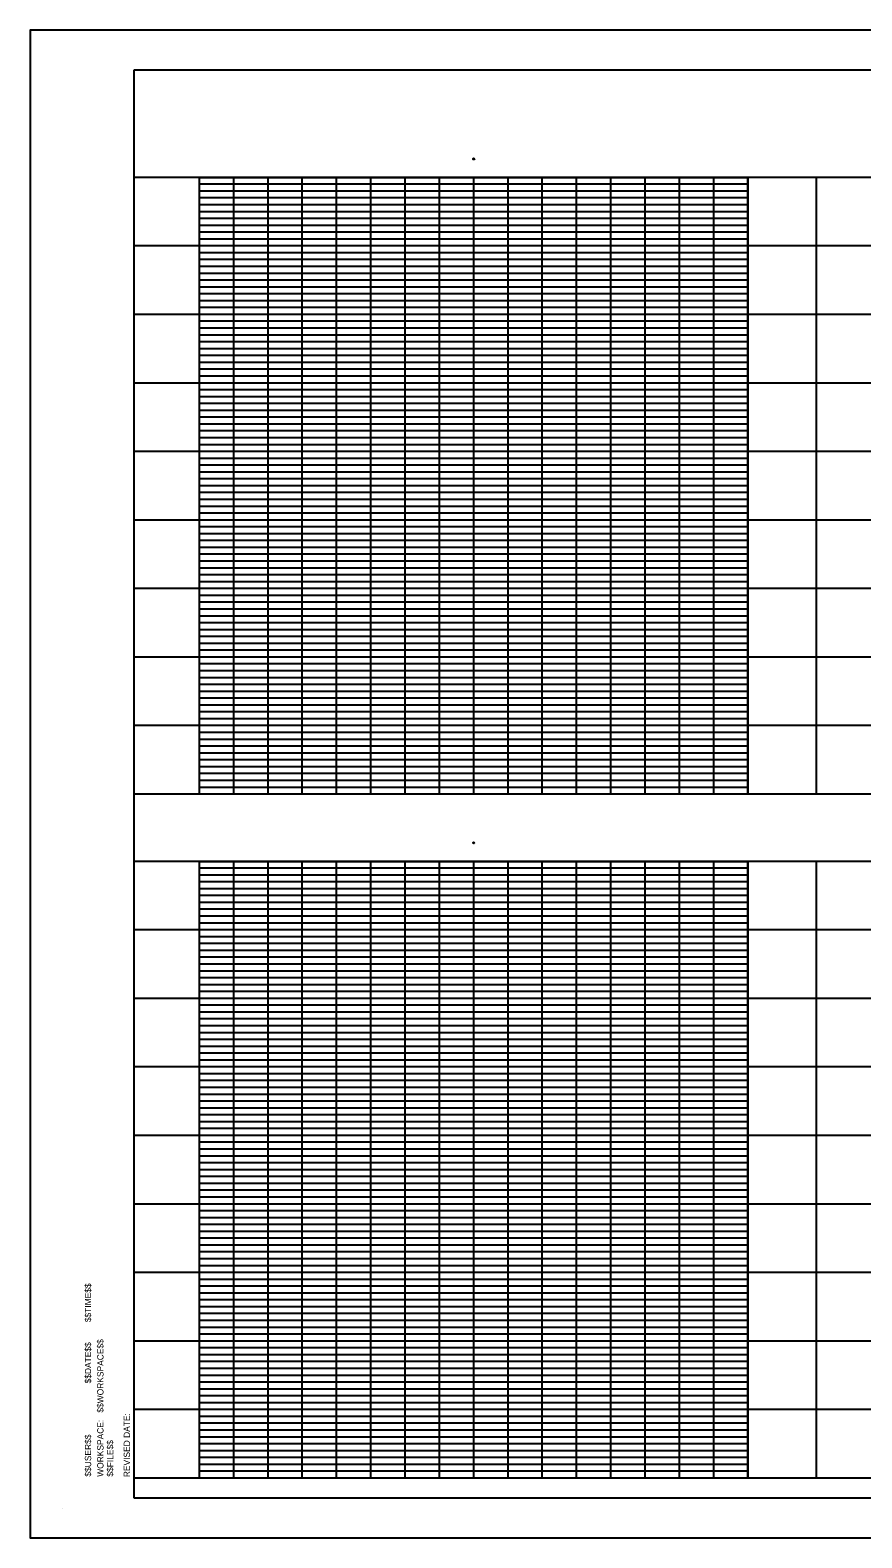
# Model space of a CAD drawing. Extents: x 1 to 1451078, y 0 to 2059437.
# Drawn here: x 1449378 to 1449985, y 2058337 to 2059437 of the extents above; entities that cross this region are included whole.
import ezdxf

# ---------------------------------------------------------------- set-up
doc = ezdxf.new("R2010")
doc.units = 0
for name, color, linetype in [('1', 7, 'Continuous'), ('G-ANNO-TEXT', 7, 'Continuous'), ('G-Border-Sheet', 7, 'Continuous'), ('G-Grid-Border-1', 7, 'Continuous'), ('G-Grid-Border-2', 7, 'Continuous'), ('G-Grid-Major-1', 7, 'Continuous'), ('G-Grid-Minor-1', 7, 'Continuous'), ('G-No Plot-Anchor', 7, 'Continuous')]:
    doc.layers.add(name, color=color, linetype=linetype)

msp = doc.modelspace()

# ---------------------------------------------------------------- linework, layer by layer
at = {"layer": '1'}
msp.add_lwpolyline([(1451078.1, 2059436.5), (1449378.1, 2059436.5), (1449378.1, 2058336.5), (1451078.1, 2058336.5)], close=True, dxfattribs=at)
at = {"layer": 'G-ANNO-TEXT'}
msp.add_line((1449401.5, 2058357.9), (1449401.5, 2058357.9), dxfattribs=at)
at = {"layer": 'G-Border-Sheet'}
for p, q in [((1449453.9, 2059407.7), (1451049.3, 2059407.7)), ((1449453.9, 2058365.4), (1449453.9, 2059407.7)), ((1451049.3, 2058365.4), (1449453.9, 2058365.4))]:
    msp.add_line(p, q, dxfattribs=at)
at = {"layer": 'G-Grid-Border-1'}
for p, q in [((1450898.5, 2059329.1), (1449453.9, 2059329.1)), ((1449951.6, 2058879.1), (1449951.6, 2059329.1)), ((1451049.3, 2058879.1), (1449453.9, 2058879.1)), ((1451049.3, 2058830.1), (1449453.9, 2058830.1)), ((1449951.6, 2058380.1), (1449951.6, 2058830.1)), ((1451049.3, 2058380.1), (1449453.9, 2058380.1))]:
    msp.add_line(p, q, dxfattribs=at)
for points in [[(1449501.6, 2059329.1), (1449901.6, 2059329.1), (1449901.6, 2058879.1), (1449501.6, 2058879.1)], [(1449501.6, 2058830.1), (1449901.6, 2058830.1), (1449901.6, 2058380.1), (1449501.6, 2058380.1)]]:
    msp.add_lwpolyline(points, close=True, dxfattribs=at)
at = {"layer": 'G-Grid-Border-2'}
for p, q in [((1450501.6, 2059329.1), (1449453.9, 2059329.1)), ((1451049.3, 2058879.1), (1449453.9, 2058879.1)), ((1451049.3, 2058830.1), (1449453.9, 2058830.1)), ((1451049.3, 2058380.1), (1449453.9, 2058380.1))]:
    msp.add_line(p, q, dxfattribs=at)
for points in [[(1449501.6, 2059329.1), (1449901.6, 2059329.1), (1449901.6, 2058879.1), (1449501.6, 2058879.1)], [(1449501.6, 2058830.1), (1449901.6, 2058830.1), (1449901.6, 2058380.1), (1449501.6, 2058380.1)]]:
    msp.add_lwpolyline(points, close=True, dxfattribs=at)
msp.add_lwpolyline([(1451001.6, 2058830.1), (1451001.6, 2058380.1), (1449501.6, 2058380.1), (1449501.6, 2058830.1)], dxfattribs=at)
at = {"layer": 'G-Grid-Major-1'}
for p, q in [((1449501.6, 2058879.1), (1449501.6, 2059329.1)), ((1449551.6, 2058879.1), (1449551.6, 2059329.1)), ((1449601.6, 2058879.1), (1449601.6, 2059329.1)), ((1449651.6, 2058879.1), (1449651.6, 2059329.1)), ((1449701.6, 2058879.1), (1449701.6, 2059329.1)), ((1449751.6, 2058879.1), (1449751.6, 2059329.1)), ((1449801.6, 2058879.1), (1449801.6, 2059329.1)), ((1449851.6, 2058879.1), (1449851.6, 2059329.1)), ((1449901.6, 2058879.1), (1449901.6, 2059329.1)), ((1449951.6, 2058879.1), (1449951.6, 2059329.1)), ((1449901.6, 2059279.1), (1449453.9, 2059279.1)), ((1450901.6, 2059279.1), (1449901.6, 2059279.1)), ((1449901.6, 2059229.1), (1449453.9, 2059229.1)), ((1450901.6, 2059229.1), (1449901.6, 2059229.1)), ((1449901.6, 2059179.1), (1449453.9, 2059179.1)), ((1451049.3, 2059179.1), (1449901.6, 2059179.1)), ((1449901.6, 2059129.1), (1449453.9, 2059129.1)), ((1451049.3, 2059129.1), (1449901.6, 2059129.1)), ((1449901.6, 2059079.1), (1449453.9, 2059079.1)), ((1451049.3, 2059079.1), (1449901.6, 2059079.1)), ((1449901.6, 2059029.1), (1449453.9, 2059029.1)), ((1451049.3, 2059029.1), (1449901.6, 2059029.1)), ((1449901.6, 2058979.1), (1449453.9, 2058979.1)), ((1451049.3, 2058979.1), (1449901.6, 2058979.1)), ((1449901.6, 2058929.1), (1449453.9, 2058929.1)), ((1451049.3, 2058929.1), (1449901.6, 2058929.1)), ((1449501.6, 2058380.1), (1449501.6, 2058830.1)), ((1449551.6, 2058380.1), (1449551.6, 2058830.1)), ((1449601.6, 2058380.1), (1449601.6, 2058830.1)), ((1449651.6, 2058380.1), (1449651.6, 2058830.1)), ((1449701.6, 2058380.1), (1449701.6, 2058830.1)), ((1449751.6, 2058380.1), (1449751.6, 2058830.1)), ((1449801.6, 2058380.1), (1449801.6, 2058830.1)), ((1449851.6, 2058380.1), (1449851.6, 2058830.1)), ((1449901.6, 2058380.1), (1449901.6, 2058830.1)), ((1449901.6, 2058780.1), (1449453.9, 2058780.1)), ((1451049.3, 2058780.1), (1449901.6, 2058780.1)), ((1449901.6, 2058730.1), (1449453.9, 2058730.1)), ((1451049.3, 2058730.1), (1449901.6, 2058730.1)), ((1449901.6, 2058680.1), (1449453.9, 2058680.1)), ((1451049.3, 2058680.1), (1449901.6, 2058680.1)), ((1449901.6, 2058630.1), (1449453.9, 2058630.1)), ((1451049.3, 2058630.1), (1449901.6, 2058630.1)), ((1449901.6, 2058580.1), (1449453.9, 2058580.1)), ((1451049.3, 2058580.1), (1449901.6, 2058580.1)), ((1449901.6, 2058530.1), (1449453.9, 2058530.1)), ((1451049.3, 2058530.1), (1449901.6, 2058530.1)), ((1449901.6, 2058480.1), (1449453.9, 2058480.1)), ((1451049.3, 2058480.1), (1449901.6, 2058480.1)), ((1449901.6, 2058430.1), (1449453.9, 2058430.1)), ((1451049.3, 2058430.1), (1449901.6, 2058430.1))]:
    msp.add_line(p, q, dxfattribs=at)
at = {"layer": 'G-Grid-Minor-1'}
for p, q in [((1449901.6, 2059324.1), (1449501.6, 2059324.1)), ((1449526.6, 2058879.1), (1449526.6, 2059329.1)), ((1449576.6, 2058879.1), (1449576.6, 2059329.1)), ((1449626.6, 2058879.1), (1449626.6, 2059329.1)), ((1449676.6, 2058879.1), (1449676.6, 2059329.1)), ((1449726.6, 2058879.1), (1449726.6, 2059329.1)), ((1449776.6, 2058879.1), (1449776.6, 2059329.1)), ((1449826.6, 2058879.1), (1449826.6, 2059329.1)), ((1449876.6, 2058879.1), (1449876.6, 2059329.1)), ((1449901.6, 2059319.1), (1449501.6, 2059319.1)), ((1449901.6, 2059314.1), (1449501.6, 2059314.1)), ((1449901.6, 2059309.1), (1449501.6, 2059309.1)), ((1449901.6, 2059304.1), (1449501.6, 2059304.1)), ((1449901.6, 2059299.1), (1449501.6, 2059299.1)), ((1449901.6, 2059294.1), (1449501.6, 2059294.1)), ((1449901.6, 2059289.1), (1449501.6, 2059289.1)), ((1449901.6, 2059284.1), (1449501.6, 2059284.1)), ((1449901.6, 2059274.1), (1449501.6, 2059274.1)), ((1449901.6, 2059269.1), (1449501.6, 2059269.1)), ((1449901.6, 2059264.1), (1449501.6, 2059264.1)), ((1449901.6, 2059259.1), (1449501.6, 2059259.1)), ((1449901.6, 2059254.1), (1449501.6, 2059254.1)), ((1449901.6, 2059249.1), (1449501.6, 2059249.1)), ((1449901.6, 2059244.1), (1449501.6, 2059244.1)), ((1449901.6, 2059239.1), (1449501.6, 2059239.1)), ((1449901.6, 2059234.1), (1449501.6, 2059234.1)), ((1449901.6, 2059224.1), (1449501.6, 2059224.1)), ((1449901.6, 2059219.1), (1449501.6, 2059219.1)), ((1449901.6, 2059214.1), (1449501.6, 2059214.1)), ((1449901.6, 2059209.1), (1449501.6, 2059209.1)), ((1449901.6, 2059204.1), (1449501.6, 2059204.1)), ((1449901.6, 2059199.1), (1449501.6, 2059199.1)), ((1449901.6, 2059194.1), (1449501.6, 2059194.1)), ((1449901.6, 2059189.1), (1449501.6, 2059189.1)), ((1449901.6, 2059184.1), (1449501.6, 2059184.1)), ((1449901.6, 2059174.1), (1449501.6, 2059174.1)), ((1449901.6, 2059169.1), (1449501.6, 2059169.1)), ((1449901.6, 2059164.1), (1449501.6, 2059164.1)), ((1449901.6, 2059159.1), (1449501.6, 2059159.1)), ((1449901.6, 2059154.1), (1449501.6, 2059154.1)), ((1449901.6, 2059149.1), (1449501.6, 2059149.1)), ((1449901.6, 2059144.1), (1449501.6, 2059144.1)), ((1449901.6, 2059139.1), (1449501.6, 2059139.1)), ((1449901.6, 2059134.1), (1449501.6, 2059134.1)), ((1449901.6, 2059124.1), (1449501.6, 2059124.1)), ((1449901.6, 2059119.1), (1449501.6, 2059119.1)), ((1449901.6, 2059114.1), (1449501.6, 2059114.1)), ((1449901.6, 2059109.1), (1449501.6, 2059109.1)), ((1449901.6, 2059104.1), (1449501.6, 2059104.1)), ((1449901.6, 2059099.1), (1449501.6, 2059099.1)), ((1449901.6, 2059094.1), (1449501.6, 2059094.1)), ((1449901.6, 2059089.1), (1449501.6, 2059089.1)), ((1449901.6, 2059084.1), (1449501.6, 2059084.1)), ((1449901.6, 2059074.1), (1449501.6, 2059074.1)), ((1449901.6, 2059069.1), (1449501.6, 2059069.1)), ((1449901.6, 2059064.1), (1449501.6, 2059064.1)), ((1449901.6, 2059059.1), (1449501.6, 2059059.1)), ((1449901.6, 2059054.1), (1449501.6, 2059054.1)), ((1449901.6, 2059049.1), (1449501.6, 2059049.1)), ((1449901.6, 2059044.1), (1449501.6, 2059044.1)), ((1449901.6, 2059039.1), (1449501.6, 2059039.1)), ((1449901.6, 2059034.1), (1449501.6, 2059034.1)), ((1449901.6, 2059024.1), (1449501.6, 2059024.1)), ((1449901.6, 2059019.1), (1449501.6, 2059019.1)), ((1449901.6, 2059014.1), (1449501.6, 2059014.1)), ((1449901.6, 2059009.1), (1449501.6, 2059009.1)), ((1449901.6, 2059004.1), (1449501.6, 2059004.1)), ((1449901.6, 2058999.1), (1449501.6, 2058999.1)), ((1449901.6, 2058994.1), (1449501.6, 2058994.1)), ((1449901.6, 2058989.1), (1449501.6, 2058989.1)), ((1449901.6, 2058984.1), (1449501.6, 2058984.1)), ((1449901.6, 2058974.1), (1449501.6, 2058974.1)), ((1449901.6, 2058969.1), (1449501.6, 2058969.1)), ((1449901.6, 2058964.1), (1449501.6, 2058964.1)), ((1449901.6, 2058959.1), (1449501.6, 2058959.1)), ((1449901.6, 2058954.1), (1449501.6, 2058954.1)), ((1449901.6, 2058949.1), (1449501.6, 2058949.1)), ((1449901.6, 2058944.1), (1449501.6, 2058944.1)), ((1449901.6, 2058939.1), (1449501.6, 2058939.1)), ((1449901.6, 2058934.1), (1449501.6, 2058934.1)), ((1449901.6, 2058924.1), (1449501.6, 2058924.1)), ((1449901.6, 2058919.1), (1449501.6, 2058919.1)), ((1449901.6, 2058914.1), (1449501.6, 2058914.1)), ((1449901.6, 2058909.1), (1449501.6, 2058909.1)), ((1449901.6, 2058904.1), (1449501.6, 2058904.1)), ((1449901.6, 2058899.1), (1449501.6, 2058899.1)), ((1449901.6, 2058894.1), (1449501.6, 2058894.1)), ((1449901.6, 2058889.1), (1449501.6, 2058889.1)), ((1449901.6, 2058884.1), (1449501.6, 2058884.1)), ((1449526.6, 2058380.1), (1449526.6, 2058830.1)), ((1449576.6, 2058380.1), (1449576.6, 2058830.1)), ((1449626.6, 2058380.1), (1449626.6, 2058830.1)), ((1449676.6, 2058380.1), (1449676.6, 2058830.1)), ((1449726.6, 2058380.1), (1449726.6, 2058830.1)), ((1449776.6, 2058380.1), (1449776.6, 2058830.1)), ((1449826.6, 2058380.1), (1449826.6, 2058830.1)), ((1449876.6, 2058380.1), (1449876.6, 2058830.1)), ((1449901.6, 2058825.1), (1449501.6, 2058825.1)), ((1449901.6, 2058820.1), (1449501.6, 2058820.1)), ((1449901.6, 2058815.1), (1449501.6, 2058815.1)), ((1449901.6, 2058810.1), (1449501.6, 2058810.1)), ((1449901.6, 2058805.1), (1449501.6, 2058805.1)), ((1449901.6, 2058800.1), (1449501.6, 2058800.1)), ((1449901.6, 2058795.1), (1449501.6, 2058795.1)), ((1449901.6, 2058790.1), (1449501.6, 2058790.1)), ((1449901.6, 2058785.1), (1449501.6, 2058785.1)), ((1449901.6, 2058775.1), (1449501.6, 2058775.1)), ((1449901.6, 2058770.1), (1449501.6, 2058770.1)), ((1449901.6, 2058765.1), (1449501.6, 2058765.1)), ((1449901.6, 2058760.1), (1449501.6, 2058760.1)), ((1449901.6, 2058755.1), (1449501.6, 2058755.1)), ((1449901.6, 2058750.1), (1449501.6, 2058750.1)), ((1449901.6, 2058745.1), (1449501.6, 2058745.1)), ((1449901.6, 2058740.1), (1449501.6, 2058740.1)), ((1449901.6, 2058735.1), (1449501.6, 2058735.1)), ((1449901.6, 2058725.1), (1449501.6, 2058725.1)), ((1449901.6, 2058720.1), (1449501.6, 2058720.1)), ((1449901.6, 2058715.1), (1449501.6, 2058715.1)), ((1449901.6, 2058710.1), (1449501.6, 2058710.1)), ((1449901.6, 2058705.1), (1449501.6, 2058705.1)), ((1449901.6, 2058700.1), (1449501.6, 2058700.1)), ((1449901.6, 2058695.1), (1449501.6, 2058695.1)), ((1449901.6, 2058690.1), (1449501.6, 2058690.1)), ((1449901.6, 2058685.1), (1449501.6, 2058685.1)), ((1449901.6, 2058675.1), (1449501.6, 2058675.1)), ((1449901.6, 2058670.1), (1449501.6, 2058670.1)), ((1449901.6, 2058665.1), (1449501.6, 2058665.1)), ((1449901.6, 2058660.1), (1449501.6, 2058660.1)), ((1449901.6, 2058655.1), (1449501.6, 2058655.1)), ((1449901.6, 2058650.1), (1449501.6, 2058650.1)), ((1449901.6, 2058645.1), (1449501.6, 2058645.1)), ((1449901.6, 2058640.1), (1449501.6, 2058640.1)), ((1449901.6, 2058635.1), (1449501.6, 2058635.1)), ((1449901.6, 2058625.1), (1449501.6, 2058625.1)), ((1449901.6, 2058620.1), (1449501.6, 2058620.1)), ((1449901.6, 2058615.1), (1449501.6, 2058615.1)), ((1449901.6, 2058610.1), (1449501.6, 2058610.1)), ((1449901.6, 2058605.1), (1449501.6, 2058605.1)), ((1449901.6, 2058600.1), (1449501.6, 2058600.1)), ((1449901.6, 2058595.1), (1449501.6, 2058595.1)), ((1449901.6, 2058590.1), (1449501.6, 2058590.1)), ((1449901.6, 2058585.1), (1449501.6, 2058585.1)), ((1449901.6, 2058575.1), (1449501.6, 2058575.1)), ((1449901.6, 2058570.1), (1449501.6, 2058570.1)), ((1449901.6, 2058565.1), (1449501.6, 2058565.1)), ((1449901.6, 2058560.1), (1449501.6, 2058560.1)), ((1449901.6, 2058555.1), (1449501.6, 2058555.1)), ((1449901.6, 2058550.1), (1449501.6, 2058550.1)), ((1449901.6, 2058545.1), (1449501.6, 2058545.1)), ((1449901.6, 2058540.1), (1449501.6, 2058540.1)), ((1449901.6, 2058535.1), (1449501.6, 2058535.1)), ((1449901.6, 2058525.1), (1449501.6, 2058525.1)), ((1449901.6, 2058520.1), (1449501.6, 2058520.1)), ((1449901.6, 2058515.1), (1449501.6, 2058515.1)), ((1449901.6, 2058510.1), (1449501.6, 2058510.1)), ((1449901.6, 2058505.1), (1449501.6, 2058505.1)), ((1449901.6, 2058500.1), (1449501.6, 2058500.1)), ((1449901.6, 2058495.1), (1449501.6, 2058495.1)), ((1449901.6, 2058490.1), (1449501.6, 2058490.1)), ((1449901.6, 2058485.1), (1449501.6, 2058485.1)), ((1449901.6, 2058475.1), (1449501.6, 2058475.1)), ((1449901.6, 2058470.1), (1449501.6, 2058470.1)), ((1449901.6, 2058465.1), (1449501.6, 2058465.1)), ((1449901.6, 2058460.1), (1449501.6, 2058460.1)), ((1449901.6, 2058455.1), (1449501.6, 2058455.1)), ((1449901.6, 2058450.1), (1449501.6, 2058450.1)), ((1449901.6, 2058445.1), (1449501.6, 2058445.1)), ((1449901.6, 2058440.1), (1449501.6, 2058440.1)), ((1449901.6, 2058435.1), (1449501.6, 2058435.1)), ((1449901.6, 2058425.1), (1449501.6, 2058425.1)), ((1449901.6, 2058420.1), (1449501.6, 2058420.1)), ((1449901.6, 2058415.1), (1449501.6, 2058415.1)), ((1449901.6, 2058410.1), (1449501.6, 2058410.1)), ((1449901.6, 2058405.1), (1449501.6, 2058405.1)), ((1449901.6, 2058400.1), (1449501.6, 2058400.1)), ((1449901.6, 2058395.1), (1449501.6, 2058395.1)), ((1449901.6, 2058390.1), (1449501.6, 2058390.1)), ((1449901.6, 2058385.1), (1449501.6, 2058385.1))]:
    msp.add_line(p, q, dxfattribs=at)
msp.add_lwpolyline([(1451001.6, 2059179.1), (1451001.6, 2058879.1), (1449501.6, 2058879.1), (1449501.6, 2059329.1)], dxfattribs=at)
at = {"layer": 'G-No Plot-Anchor'}
for centre in [(1449701.6, 2059342.6), (1449701.6, 2058843.6)]:
    msp.add_circle(centre, 0.5, dxfattribs=at)

# ---------------------------------------------------------------- texts
at = {"layer": 'G-ANNO-TEXT'}
for s, p in [('$$TIME$$', (1449422.6, 2058493.9)), ('$$DATE$$', (1449422.6, 2058449.2)), ('$$WORKSPACE$$', (1449431.6, 2058427.9)), ('WORKSPACE:', (1449431.6, 2058381.1)), ('REVISED DATE:', (1449450.9, 2058380.8)), ('$$USER$$', (1449422.6, 2058381.2)), ('$$FILE$$', (1449438.7, 2058381.2))]:
    msp.add_text(s, height=4.59, rotation=90, dxfattribs=at).set_placement(p)

doc.saveas('drawing.dxf')
